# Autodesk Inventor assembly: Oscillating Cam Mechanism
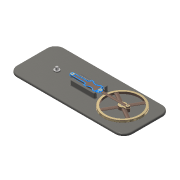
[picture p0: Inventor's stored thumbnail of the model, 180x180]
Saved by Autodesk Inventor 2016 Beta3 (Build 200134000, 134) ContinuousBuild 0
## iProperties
Created: 2016-02
Part Number: Oscillating Cam Mechanism
Document SubType Name: Assembly
Designer: User
Author: User
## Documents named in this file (10)
- C:\Users\Gaurav\Downloads\Compressed\oscillating-cam-mechanism-1.snapshot.1\Oscillating Cam Mechanism.iam
- C:\Users\Gaurav\Downloads\Compressed\oscillating-cam-mechanism-1.snapshot.1\Basic Plate.ipt
- C:\Users\Gaurav\Downloads\Compressed\oscillating-cam-mechanism-1.snapshot.1\DIN 625 SKF - SKF 625.ipt
- C:\Users\Gaurav\Downloads\Compressed\oscillating-cam-mechanism-1.snapshot.1\Tappet.ipt
- C:\Users\Gaurav\Downloads\Compressed\oscillating-cam-mechanism-1.snapshot.1\Shaft 12x26.ipt
- C:\Users\Gaurav\Downloads\Compressed\oscillating-cam-mechanism-1.snapshot.1\Shaft 5x13.ipt
- C:\Users\Gaurav\Downloads\Compressed\oscillating-cam-mechanism-1.snapshot.1\Oscillating Wheel.ipt
- C:\Users\Gaurav\Downloads\Compressed\oscillating-cam-mechanism-1.snapshot.1\Lever 121.ipt
- C:\Users\Gaurav\Downloads\Compressed\oscillating-cam-mechanism-1.snapshot.1\Shaft 5x8.ipt
- C:\Users\Gaurav\Downloads\Compressed\oscillating-cam-mechanism-1.snapshot.1\Shaft 5x22.ipt
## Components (10 placed, 9 different names)
1. Basic Plate:1 — Mate:1, Flush:1, Insert:6
2. DIN 625 SKF - SKF 625:1 — Insert:3, Insert:4
3. Tappet:1 — Insert:4, Mate:1, Flush:1, Insert:7, Insert:9
4. Oscillating Wheel:1 — Insert:6, Mate:2, Insert:8
5. Lever 121:1 — Insert:7, Mate:2, Insert:10
6. Shaft 5x13:1 — Insert:3
7. Shaft 12x26:1
8. Shaft 12x26:2 — Insert:8
9. Shaft 5x8:1 — Insert:9
10. Shaft 5x22:1 — Insert:10
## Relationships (10: Insert 7, Mate 2, Flush 1)
- Insert:3: DIN 625 SKF - SKF 625:1 ↔ Shaft 5x13:1
- Insert:4: DIN 625 SKF - SKF 625:1 ↔ Tappet:1
- Mate:1: Basic Plate:1 ↔ Tappet:1
- Flush:1: Basic Plate:1 ↔ Tappet:1
- Insert:6: Basic Plate:1 ↔ Oscillating Wheel:1
- Insert:7: Tappet:1 ↔ Lever 121:1
- Mate:2: Oscillating Wheel:1 ↔ Lever 121:1
- Insert:8: Oscillating Wheel:1 ↔ Shaft 12x26:2
- Insert:9: Tappet:1 ↔ Shaft 5x8:1
- Insert:10: Lever 121:1 ↔ Shaft 5x22:1
